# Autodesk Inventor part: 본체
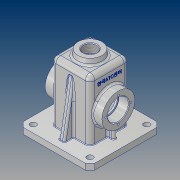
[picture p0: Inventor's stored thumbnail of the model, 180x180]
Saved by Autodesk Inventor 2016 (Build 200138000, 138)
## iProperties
Created: 2018-10
Part Number: 본체
Material: 알루미늄 6061
Document SubType Name: Modeling
Designer: user
Density: 2.7 g/cm^3
Appearance: 알루미늄 - 평지
Mass: 794.228 g
Surface Area: 899.5 cm^2
Volume: 294.158 cm^3
Author: user
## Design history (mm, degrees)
sketch "스케치1"
  geometry: L1 (60, 60)-(-60, 60); L2 (-60, 60)-(-60, -60); L3 (-60, -60)-(60, -60); L4 (60, -60)-(60, 60); L5 (60, 60)-(-60, -60); L6 (-60, 60)-(60, -60); 1 further point
  constraints: 12 end point, 2 midpoint, 2 parallel, 1 horizontal, 1 perpendicular
  dimensions: "d0" = 120 distance of L3.end L2.end; "d1" = 120 distance of L2.end L1.end
extrude "돌출1" new body sketch "스케치1" distance "d2" = 10; taper "d3" = 0 deg
sketch "스케치2"
  geometry: L1 (32.5, -32.5)-(-32.5, -32.5); L2 (-32.5, -32.5)-(-32.5, 32.5); L3 (-32.5, 32.5)-(32.5, 32.5); L4 (32.5, 32.5)-(32.5, -32.5); L5 (32.5, -32.5)-(-32.5, 32.5); L6 (-32.5, -32.5)-(32.5, 32.5); 1 further point
  constraints: 12 end point, 2 midpoint, 2 parallel, 1 horizontal, 1 perpendicular
  dimensions: "d4" = 65 distance of L2.end L3.end; "d5" = 65 distance of L1.end L2.end
extrude "돌출2" join sketch "스케치2" distance "d6" = 100; taper "d7" = 0 deg
fillet "모깎기1" dims "d8" = 8
fillet "모깎기2" dims "d9" = 8
feature "쉘1" dims "d10" = 10, "d11" = 5
sketch "스케치3"
  geometry: L1 (49, 0)-(0, 0) reference; C1 r 27.5 at (24.5, 55); 2 further points
  constraints: 1 centre point, 1 midpoint, 1 vertical alignment
  dimensions: "d12" = 55 diameter of C1; "d13" = 55 distance from line of L1 C1.centre
extrude "돌출3" join sketch "스케치3" distance "d14" = 20; taper "d15" = 0 deg
hole "구멍1" diameter "d18" = 30; stored, may be unused: countersink angle "d22" = 90 deg, drill point angle "d24" = 0 deg; dims "d16" = 10, "d17" = 10, "d19" = 6, "d20" = 35, "d21" = 17, "d23" = 20
node "작업 평면1"
sketch "스케치4"
  geometry: L1 (-35.5, -102)-(-35.5, -92) reference; L2 (-35.5, -92)-(-8, -92) reference; L3 (-8, -92)-(-8, 0) reference; L4 (0, 8)-(49, 8) reference; L5 (57, 0)-(57, -92) reference; L6 (57, -92)-(84.5, -92) reference; L7 (84.5, -92)-(84.5, -102) reference; L8 (84.5, -102)-(52, -102) reference; L9 (52, -102)-(52, 0) reference; L10 (49, 3)-(0, 3) reference; L11 (-3, 0)-(-3, -102) reference; L12 (-3, -102)-(-35.5, -102) reference; L13 (57, -4.095)-(72.5, -92); L14 (-8, -4.095)-(-23.5, -92); A1 r 8 centre (0, 0) between (0, 8) and (-8, 0) reference; A2 r 8 centre (49, 0) between (57, 0) and (49, 8) reference; A3 r 3 centre (49, 0) between (52, 0) and (49, 3) reference; A4 r 3 centre (0, 0) between (0, 3) and (-3, 0) reference; 1 further point
  constraints: 4 end point, 4 point on line
  dimensions: "d25" = 12 distance from line of L7 L13.end; "d26" = 10 deg angle of L7 L13; "d27" = 12 distance from line of L1 L14.end; "d28" = 10 deg angle of L1 L14
extrude "돌출4" join sketch "스케치4" distance "d29" = 5; taper "d30" = 0 deg
node "작업 평면2"
sketch "스케치5"
  geometry: L1 (84.5, -92)-(-35.5, -92) reference; L2 (52, 0)-(52, -102) reference; L3 (52, -92)-(67, -92); L4 (67, -92)-(67, -71); L5 (67, -71)-(52, -71); L6 (52, -71)-(52, -92); 1 further point
  constraints: 8 end point, 2 parallel, 2 point on line, 1 horizontal, 1 perpendicular
  dimensions: "d31" = 15 distance of L4.end L5.end; "d32" = 21 distance of L3.end L4.end
extrude "돌출5" join sketch "스케치5" stored distance "d33" = 6; taper "d34" = 0 deg
sketch "스케치6"
  geometry: L1 (-47.5, 47.5)-(47.5, 47.5); L2 (47.5, 47.5)-(47.5, -47.5); L3 (47.5, -47.5)-(-47.5, -47.5); L4 (-47.5, -47.5)-(-47.5, 47.5); L5 (-47.5, 47.5)-(47.5, -47.5); L6 (47.5, 47.5)-(-47.5, -47.5); 5 further points
  constraints: 12 end point, 4 coincident, 2 midpoint, 2 parallel, 1 horizontal, 1 perpendicular
  dimensions: "d35" = 95 distance of L2.end L3.end; "d36" = 95 distance of L1.end L2.end
hole "구멍2" sketch "스케치6" at (47.5, -47.5), (-47.5, -47.5), (-47.5, 47.5), (47.5, 47.5) diameter "d37" = 10; stored, may be unused: countersink angle "d41" = 90 deg, drill point angle "d43" = 0 deg; dims "d38" = 6, "d39" = 35, "d40" = 17, "d42" = 20
sketch "스케치7"
  geometry: C1 r 17.5 at (0, 0) reference; 2 further points
  constraints: 1 vertical alignment
  dimensions: "d44" = 21 distance of C1.centre point (0, 21)
hole "구멍3" sketch "스케치7" at (0, 21) diameter "d45" = 3.242; stored, may be unused: countersink angle "d49" = 90 deg, drill point angle "d51" = 118 deg; dims "d46" = 8, "d47" = 35, "d48" = 17, "d50" = 10
node "작업 평면4"
sketch "스케치8"
  geometry: C1 r 20 at (0, 0); 1 further point
  constraints: 1 centre point, 1 coincident
  dimensions: "d56" = 40 diameter of C1
extrude "돌출6" join sketch "스케치8" stored distance "d57" = 6; taper "d58" = 7 deg
hole "구멍4" diameter "d61" = 22.835; stored, may be unused: countersink angle "d65" = 90 deg, drill point angle "d67" = 0 deg; dims "d59" = 10, "d60" = 10, "d62" = 50, "d63" = 35, "d64" = 17, "d66" = 59.3
chamfer "모따기1" distance "d68" = 8; stored, may be unused: second distance "d69" = 2, angle "d70" = 45 deg
chamfer "모따기2" distance "d71" = 8; stored, may be unused: second distance "d72" = 2, angle "d73" = 45 deg
chamfer "모따기3" distance "d74" = 8; stored, may be unused: second distance "d75" = 2, angle "d76" = 45 deg
chamfer "모따기4" distance "d77" = 8; stored, may be unused: second distance "d78" = 2, angle "d79" = 45 deg
fillet "모깎기3" dims "d80" = 3
fillet "모깎기4" dims "d81" = 3
fillet "모깎기5" dims "d82" = 3, "d83" = 1, "d84" = 0.3
chamfer "모따기5" distance "d85" = 1; stored, may be unused: second distance "d86" = 2, angle "d87" = 45 deg
chamfer "모따기6" distance "d88" = 1; stored, may be unused: second distance "d89" = 2, angle "d90" = 45 deg
chamfer "모따기7" distance "d91" = 1; stored, may be unused: second distance "d92" = 2, angle "d93" = 45 deg
sketch "스케치9"
  geometry: L1 (3.761, -4.998)-(45.239, -4.998); L2 (45.239, -4.998)-(45.239, -11.002); L3 (45.239, -11.002)-(3.761, -11.002); L4 (3.761, -11.002)-(3.761, -4.998); L5 (3.761, -11.002)-(45.239, -4.998); L6 (3.761, -4.998)-(45.239, -11.002); L7 (4.5, 18)-(44.5, 18) reference; L8 (-8, 0)-(-8, -91) reference; 2 further points
  constraints: 4 end point, 1 midpoint, 2 other
  dimensions: "d94" = 26 distance from line of L7 point (24.5, -8); "d95" = 32.5 distance from line of point (24.5, -8) L8
feature "엠보싱1" sketch "스케치9" dims "d96" = 0.5, "d97" = 0
node "솔리드1"
pattern_circular "원형 패턴1" dims angle "d53" = 360 deg
mirror "대칭1"
node "절단 모서리 투영1"
